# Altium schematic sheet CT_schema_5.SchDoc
size 254 x 245 mm
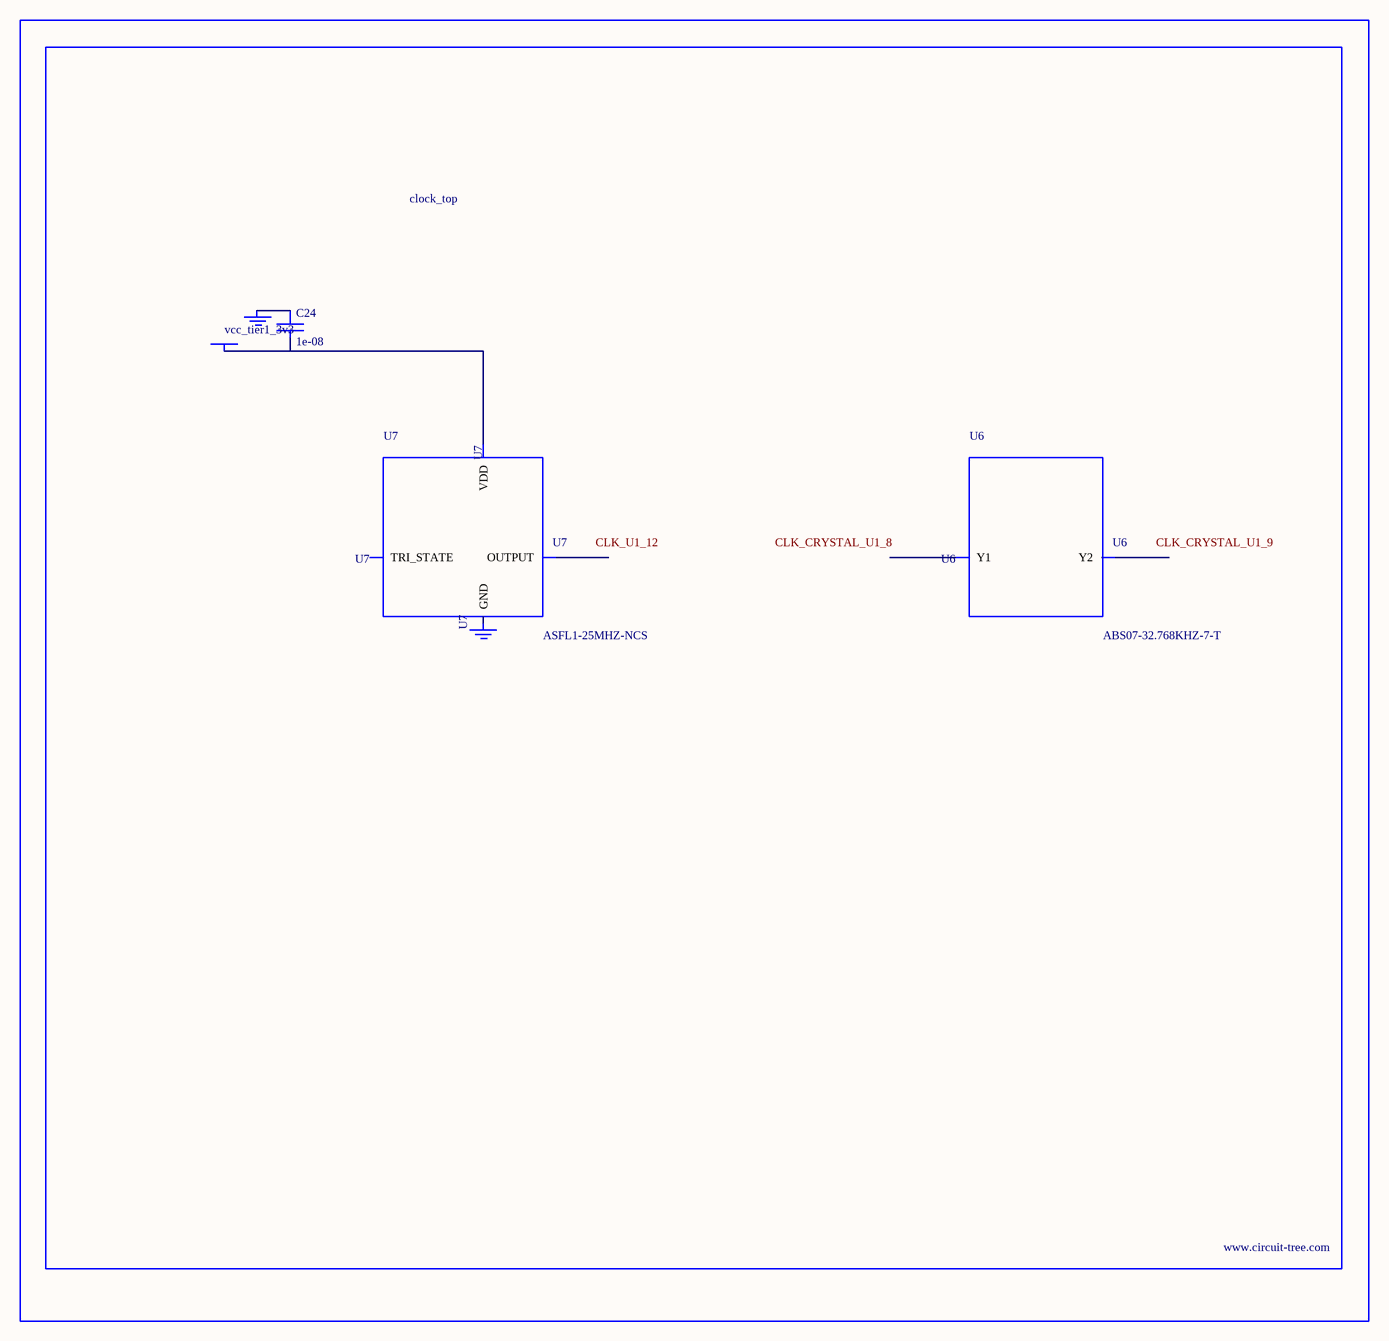
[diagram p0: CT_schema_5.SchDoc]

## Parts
BORDER4  (no value)
C24  1e-08  [C0402]
GND_INSTANCE_4_0  (no value)
GND_INSTANCE_4_1  (no value)
POWER_INSTANCE_4_0  vcc_tier1_3v3
U6  ABS07-32.768KHZ-7-T  [ABS07-32.768KHZ-7-T]
U7  ASFL1-25MHZ-NCS  [ASFL1]

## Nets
NetC24_1: C24.1 GND_INSTANCE_4_0.0(GND)
NetC24_2: C24.2 POWER_INSTANCE_4_0.0(PWR) U7.4(VDD)

Not connected (* = marked no-connect by the designer): GND_INSTANCE_4_1 0(GND); U6 1(Y1) 2(Y2); U7 1(TRI_STATE) 2(GND) 3(OUTPUT)

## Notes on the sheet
- Labels drawn without touching a wire or pin: CLK_CRYSTAL_U1_8, CLK_CRYSTAL_U1_9, CLK_U1_12

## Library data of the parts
BORDER4 = BORDER_PAGE4
C24 = C0402C103K3RAC
GND_INSTANCE_4_0 GND_INSTANCE_4_1 = GND
POWER_INSTANCE_4_0 = PWR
